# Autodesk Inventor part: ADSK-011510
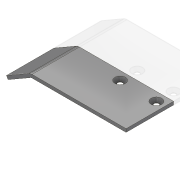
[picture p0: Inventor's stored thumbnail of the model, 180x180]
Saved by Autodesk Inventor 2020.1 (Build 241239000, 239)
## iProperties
Created: 2000-02
Part Number: ADSK-011510
Material: 1.0312 DC05
Description: FSHTPH,SS,CP,01,044,006,030,PLATE,GUIDE
Document SubType Name: Tôlerie
Designer: sspink
Density: 1 g/cm^3
Sheet Metal Rule: Stahlblech 1.0312 - DC05 -   3.0 mm
Appearance: Stahl
Mass: 15.2452 g
Surface Area: 112.812 cm^2
Volume: 15.2452 cm^3
Flat Pattern Width: 9.62983 cm
Flat Pattern Length: 12.1793 cm
Flat Pattern Area: 117.285 cm^2
Sheet Metal Width: 96,298 mm
Sheet Metal Length: 121,793 mm
Sheet Metal Area: 11728,503 mm^2
Control State: 0
Master: False
Checked Out: False
Shininess: 57.0
Length Units: 11269
Angle Units: 11279
Time Units: 11290
Mass Units: 11283
Length Display Precision: 3
Angle Display Precision: 2
Compacted: True
Cutlength: 1.75 X 4.53 (8 SI)
Material Desc: SHEET,S/S, 11 GA
Material_number: A084638
G_L: 121,8x96,3 mm
Thickness: 3,000 mm
Dimensions: 112,2x15,5x45 mm
Mass: 0,015 kg
Semi finished: Stahlblech 1.0312 - DC05 -   3.0 mm
Density: 0.0
Volumn: 0.0
Area: 0.0
PropertySet Name: Model Information
Author: sspink
Revision Number: -
Title: FSHTPH,SS,CP,01,044,006,030,PLATE,GUIDE
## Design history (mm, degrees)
node "Solide1"
  node "Extrusion1" dims "d2" = 45, "d3" = 0
  node "Hole1" dims "d11" = 4.5, "d12" = 10, "d13" = 6.35, "d14" = 90 deg, "d15" = 19.05, "d16" = 118 deg, "d23" = 6
  node "Bend1" dims "d18" = 3 (= BendRadius), "d19" = 3 (= BendReliefWidth), "d20" = 1.5 (= BendReliefDepth), "d21" = 6 (= MinimumRemnant), "d22" = 3 (= Thickness), "SeamGap" = 0.00508, "MinimumRemnant" = 6 (= 2 x Thickness), "BendReliefWidth" = 3 (= Thickness)
sketch "Sketch1"
  geometry: L1 (0, 0)-(89, 0); L2 (89, 0)-(89, 3); L3 (89, 3)-(0, 3); L4 (0, 3)-(0, 0); L5 (0, 0)-(-21.651, -12.5); L6 (-21.651, -12.5)-(-23.151, -9.902); L7 (-23.151, -9.902)-(-0.804, 3); L8 (0, 3)-(-0.804, 3)
  constraints: 16 end point, 3 parallel, 3 perpendicular, 1 horizontal
  dimensions: "d0" = 3 distance between parallel lines of L1 L3; "d1" = 89 distance of L2.end L3.end; "d4" = 25 distance of L1.start L5.end; "d5" = 3 distance between parallel lines of L5 L7; "d6" = 150 deg angle of L1 L5
sketch "Sketch2"
  geometry: L1 (89.804, 0)-(89.804, -45) reference; L2 (89.804, 0)-(0, 0) reference; 2 further points
  constraints: 1 horizontal alignment
  dimensions: "d7" = 8 distance from line of point (81.804, -8) L1; "d17" = 8 distance from line of point (81.804, -8) L2; "d24" = 34 distance of point (81.804, -8) point (47.804, -8)
node "FlatPattern"
node "Corps solides"
node "Corps surfaciques"
feature "Extrusion_mise_à_plat2" dims "d0" = 3 (derived)
other parameters: "thickness" = 3.175 [user parameter], "Thickness" = 3 (derived), "BendRadius" = 3 (= Thickness), "BendReliefDepth" = 1.5 (= 0.5 x Thickness), "CornerReliefSize" = 12 (= 4 x Thickness), "TransitionRadius" = 3 (= BendRadius), "TailleRayonJacobi" = 3 (= BendRadius), "TailleJeu" = 3 (= Thickness)
